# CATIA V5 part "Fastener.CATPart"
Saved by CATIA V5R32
Part number: Fastener
Bounding box of the stored display mesh (mm): x -5 to 5, y -5 to 5, z -48 to 0
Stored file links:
  D:\PROJECTS\Project 2022\CATIA V5 6R 2022\Resources\Tutorial Files\c14_catia_v5_6r2022_tut\c14tut2\c14tut2.CATParts\Fastener.CATPart
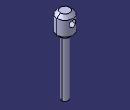
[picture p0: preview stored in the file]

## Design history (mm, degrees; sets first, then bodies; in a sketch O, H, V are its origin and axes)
Body1 (main body)
  Sketch1 on xy-plane, origin (0, 0, 0), H (1, 0, 0), V (0, 1, 0)
    circle A1 centre (0, 0) radius 5
    circle A2 centre (0, 0) radius 2
    radius A2 = 2
    radius A1 = 5
  MultiPad1: profile Sketch1, domains (length 0 / length 48; length 0 / length 13)
  Chamfer1: length 2, angle 45, on 2 edges
  Chamfer2: length 0.508, angle 45, on 1 edge
  Sketch2 on zx-plane, origin (-1.612, 0, 1.612), H (1, 0, 0), V (0, 0, -1)
    point P1 (1.612, 6.35)
    reference intersected line E1 through (1.612, 0) direction (0, 1) from yz-plane
    distance P1 H = 6.35
    coincidence: E1 P1
  Hole1: placed by Sketch2, at (0, 0, -4.738) direction (0, -1, 0), diameter 4, depth 10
